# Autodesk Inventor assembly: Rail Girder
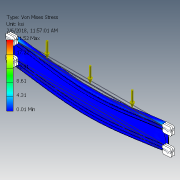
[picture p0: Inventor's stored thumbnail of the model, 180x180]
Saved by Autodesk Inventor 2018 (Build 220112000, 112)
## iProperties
Created: 2018-02
Part Number: Rail Girder
Document SubType Name: Assembly
Designer: STK
Author: STK
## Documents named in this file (4)
- D:\SolidWorks\Through Truss\Rail Girder\Rail Girder.iam
- D:\SolidWorks\Through Truss\Rail Girder\Web RG.ipt
- D:\SolidWorks\Through Truss\Rail Girder\Angle 6 X 6.ipt
- D:\SolidWorks\Through Truss\Rail Girder\Plate For Riveting.ipt
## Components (9 placed, 3 different names)
1. Web RG:1 — Mate:1, Mate:2, Flush:1, Mate:3, Flush:3, Mate:4, Mate:5, Flush:8, Mate:6, Mate:7, Flush:11
2. Angle 6 X 6:1 — Mate:3, Flush:3, Flush:4, Flush:5, Flush:6
3. Angle 6 X 6:2 — Mate:4, Flush:5, Flush:6, Flush:7
4. Angle 6 X 6:3 — Mate:5, Flush:7, Flush:8, Flush:9, Flush:10
5. Angle 6 X 6:4 — Mate:6, Flush:9, Flush:10
6. Plate For Riveting:1 — Mate:7, Flush:11, Flush:12
7. Plate For Riveting:2 — Flush:13
8. Plate For Riveting:3 — Flush:14
9. Plate For Riveting:4 — Flush:15
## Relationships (21: Flush 14, Mate 7)
- Mate:1: Web RG:1
- Mate:2: Web RG:1
- Flush:1: Web RG:1
- Mate:3: Web RG:1 ↔ Angle 6 X 6:1
- Flush:3: Web RG:1 ↔ Angle 6 X 6:1
- Flush:4: Angle 6 X 6:1
- Mate:4: Web RG:1 ↔ Angle 6 X 6:2
- Flush:5: Angle 6 X 6:1 ↔ Angle 6 X 6:2
- Flush:6: Angle 6 X 6:1 ↔ Angle 6 X 6:2
- Mate:5: Web RG:1 ↔ Angle 6 X 6:3
- Flush:7: Angle 6 X 6:2 ↔ Angle 6 X 6:3
- Flush:8: Web RG:1 ↔ Angle 6 X 6:3
- Mate:6: Web RG:1 ↔ Angle 6 X 6:4
- Flush:9: Angle 6 X 6:3 ↔ Angle 6 X 6:4
- Flush:10: Angle 6 X 6:3 ↔ Angle 6 X 6:4
- Mate:7: Web RG:1 ↔ Plate For Riveting:1
- Flush:11: Web RG:1 ↔ Plate For Riveting:1
- Flush:12: Plate For Riveting:1
- Flush:13: Plate For Riveting:2
- Flush:14: Plate For Riveting:3
- Flush:15: Plate For Riveting:4
## Named parameters: sa_0 = 1.03005e+08 mm, sa_1 = 2082.8 mm, sa_2 = 457.2 mm, sa_3 = 0, sa_4 = 1.03005e+08 mm, sa_5 = 0, sa_6 = 457.2 mm, sa_7 = 0, sa_8 = 1.03005e+08 mm, sa_9 = -2133.6 mm, sa_10 = 457.2 mm, sa_11 = 0
